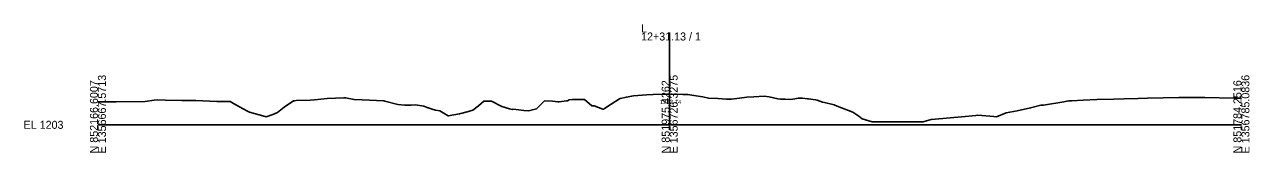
# Model space of a CAD drawing. Extents: x -26 to 4603, y -10 to 4066.
# Drawn here: x 4174.3 to 4602.8, y -9.7 to 35.1 of the extents above; entities that cross this region are included whole.
import ezdxf

# ---------------------------------------------------------------- set-up
doc = ezdxf.new("R2010")
doc.units = 0
for name, color, linetype in [('Exist Cross Section Cell', 7, 'Continuous'), ('Exist XS Center Line Elevation Label', 7, 'Continuous'), ('Exist XS Ground Line', 7, 'Continuous')]:
    doc.layers.add(name, color=color, linetype=linetype)

msp = doc.modelspace()

# ---------------------------------------------------------------- linework, layer by layer
at = {"layer": 'Exist Cross Section Cell'}
for p, q in [((4400, 0), (4400, 32.31)), ((4200, 0), (4400, 0)), ((4400, 0), (4600, 0))]:
    msp.add_line(p, q, dxfattribs=at)
at = {"layer": 'Exist XS Ground Line'}
msp.add_lwpolyline([(4200, 8.03), (4202.07, 8.03), (4204.64, 8.07), (4206.32, 8.05), (4216.5, 8.13), (4219.67, 8.61), (4220.67, 8.75), (4223.61, 8.63), (4229.4, 8.52), (4234.27, 8.47), (4241.6, 8.12), (4246.25, 8.11), (4247.47, 7.44), (4249.49, 6.31), (4252.09, 4.95), (4252.97, 4.48), (4258.47, 2.92), (4258.79, 2.83), (4261.2, 3.65), (4262.85, 4.35), (4265.2, 6.2), (4268.37, 8.35), (4268.75, 8.42), (4269.4, 8.47), (4274.24, 8.64), (4275.75, 8.73), (4280.24, 9.22), (4285.99, 9.45), (4286.61, 9.41), (4289.64, 8.9), (4292.38, 8.75), (4299.97, 8.4), (4300.4, 8.27), (4304.94, 7.07), (4307.32, 6.84), (4309.56, 6.84), (4311.13, 6.99), (4313.97, 6.51), (4315.17, 6.06), (4316.93, 5.46), (4318.07, 5.07), (4319.6, 4.84), (4322.57, 3.13), (4326.53, 3.8), (4329.6, 4.65), (4331.1, 5.11), (4333.14, 6.63), (4334.96, 8.23), (4335.35, 8.28), (4337.69, 8.22), (4341.33, 6.44), (4343.92, 5.64), (4344.85, 5.4), (4345.25, 5.45), (4347.21, 5.23), (4349.01, 5.01), (4350.48, 4.84), (4351.14, 4.99), (4353.39, 5.57), (4356.25, 8.39), (4359.01, 8.3), (4360.93, 8.08), (4361.3, 8.04), (4363.96, 8.43), (4364.27, 8.43), (4364.8, 8.8), (4365.91, 8.82), (4370.24, 8.91), (4372.79, 6.67), (4373.56, 6.61), (4376.67, 5.44), (4376.92, 5.5), (4377.26, 5.7), (4379.55, 7.26), (4382.41, 9.1), (4382.72, 9.26), (4384.89, 9.68), (4386.66, 10.02), (4387.36, 10.16), (4391.86, 10.54), (4394.24, 10.56), (4398.94, 10.77), (4400, 10.74), (4404.65, 10.63), (4406.35, 10.61), (4408.5, 10.27), (4411.55, 9.76), (4413.62, 9.29), (4416.86, 9.24), (4419.83, 8.98), (4421.58, 8.99), (4424.46, 9.38), (4427.05, 9.67), (4429.5, 9.82), (4433.05, 10), (4434.77, 9.77), (4437.85, 9.05), (4438.78, 9.02), (4440.42, 8.94), (4442.33, 8.84), (4443.83, 9.09), (4444.99, 9.28), (4445.51, 9.37), (4446.47, 9.35), (4448.17, 9.12), (4448.56, 9.08), (4450.16, 8.91), (4451.13, 8.76), (4451.55, 8.67), (4452.5, 8.25), (4453.43, 7.88), (4454.11, 7.78), (4457.51, 6.95), (4458.54, 6.49), (4464.09, 4.4), (4466.18, 3.02), (4467.37, 2.05), (4468.46, 1.71), (4470.89, 1.07), (4475.46, 1.07), (4486.99, 1.07), (4488.17, 1.07), (4488.69, 1.07), (4489.08, 1.18), (4491.48, 1.89), (4492.86, 2.02), (4502.12, 2.8), (4507.13, 3.29), (4507.81, 3.33), (4513.36, 2.92), (4514.29, 2.85), (4517.74, 4.15), (4521.54, 4.84), (4526.24, 5.91), (4529.86, 6.82), (4530.76, 6.93), (4537.9, 8.08), (4539.05, 8.31), (4539.61, 8.38), (4540.55, 8.4), (4544.7, 8.65), (4549.42, 8.91), (4555.37, 9.03), (4559.04, 9.04), (4563.88, 9.17), (4567.17, 9.32), (4578.08, 9.55), (4578.78, 9.57), (4579.29, 9.58), (4587.27, 9.52), (4597.39, 9.37), (4599.47, 9.34), (4600, 9.33)], dxfattribs=at)

# ---------------------------------------------------------------- texts
at = {"layer": 'Exist Cross Section Cell'}
for s, p in [('L', (4390, 32.31)), ('12+31.13 / 1', (4390, 29.51)), ('EL 1203', (4174, -1.4))]:
    msp.add_text(s, height=2.8, dxfattribs=at).set_placement(p)
for s, p in [('E 1356667.5713', (4202.8, -10)), ('E 1356726.3275', (4402.8, -10)), ('E 1356785.0836', (4602.8, -10)), ('N 852166.6007', (4200, -10)), ('N 851975.4262', (4400, -10)), ('N 851784.2516', (4600, -10))]:
    msp.add_text(s, height=2.8, rotation=90, dxfattribs=at).set_placement(p)
at = {"layer": 'Exist XS Center Line Elevation Label'}
msp.add_text('1213.74', height=1.5, dxfattribs=at).set_placement((4396.56, 7.24))

doc.saveas('drawing.dxf')
